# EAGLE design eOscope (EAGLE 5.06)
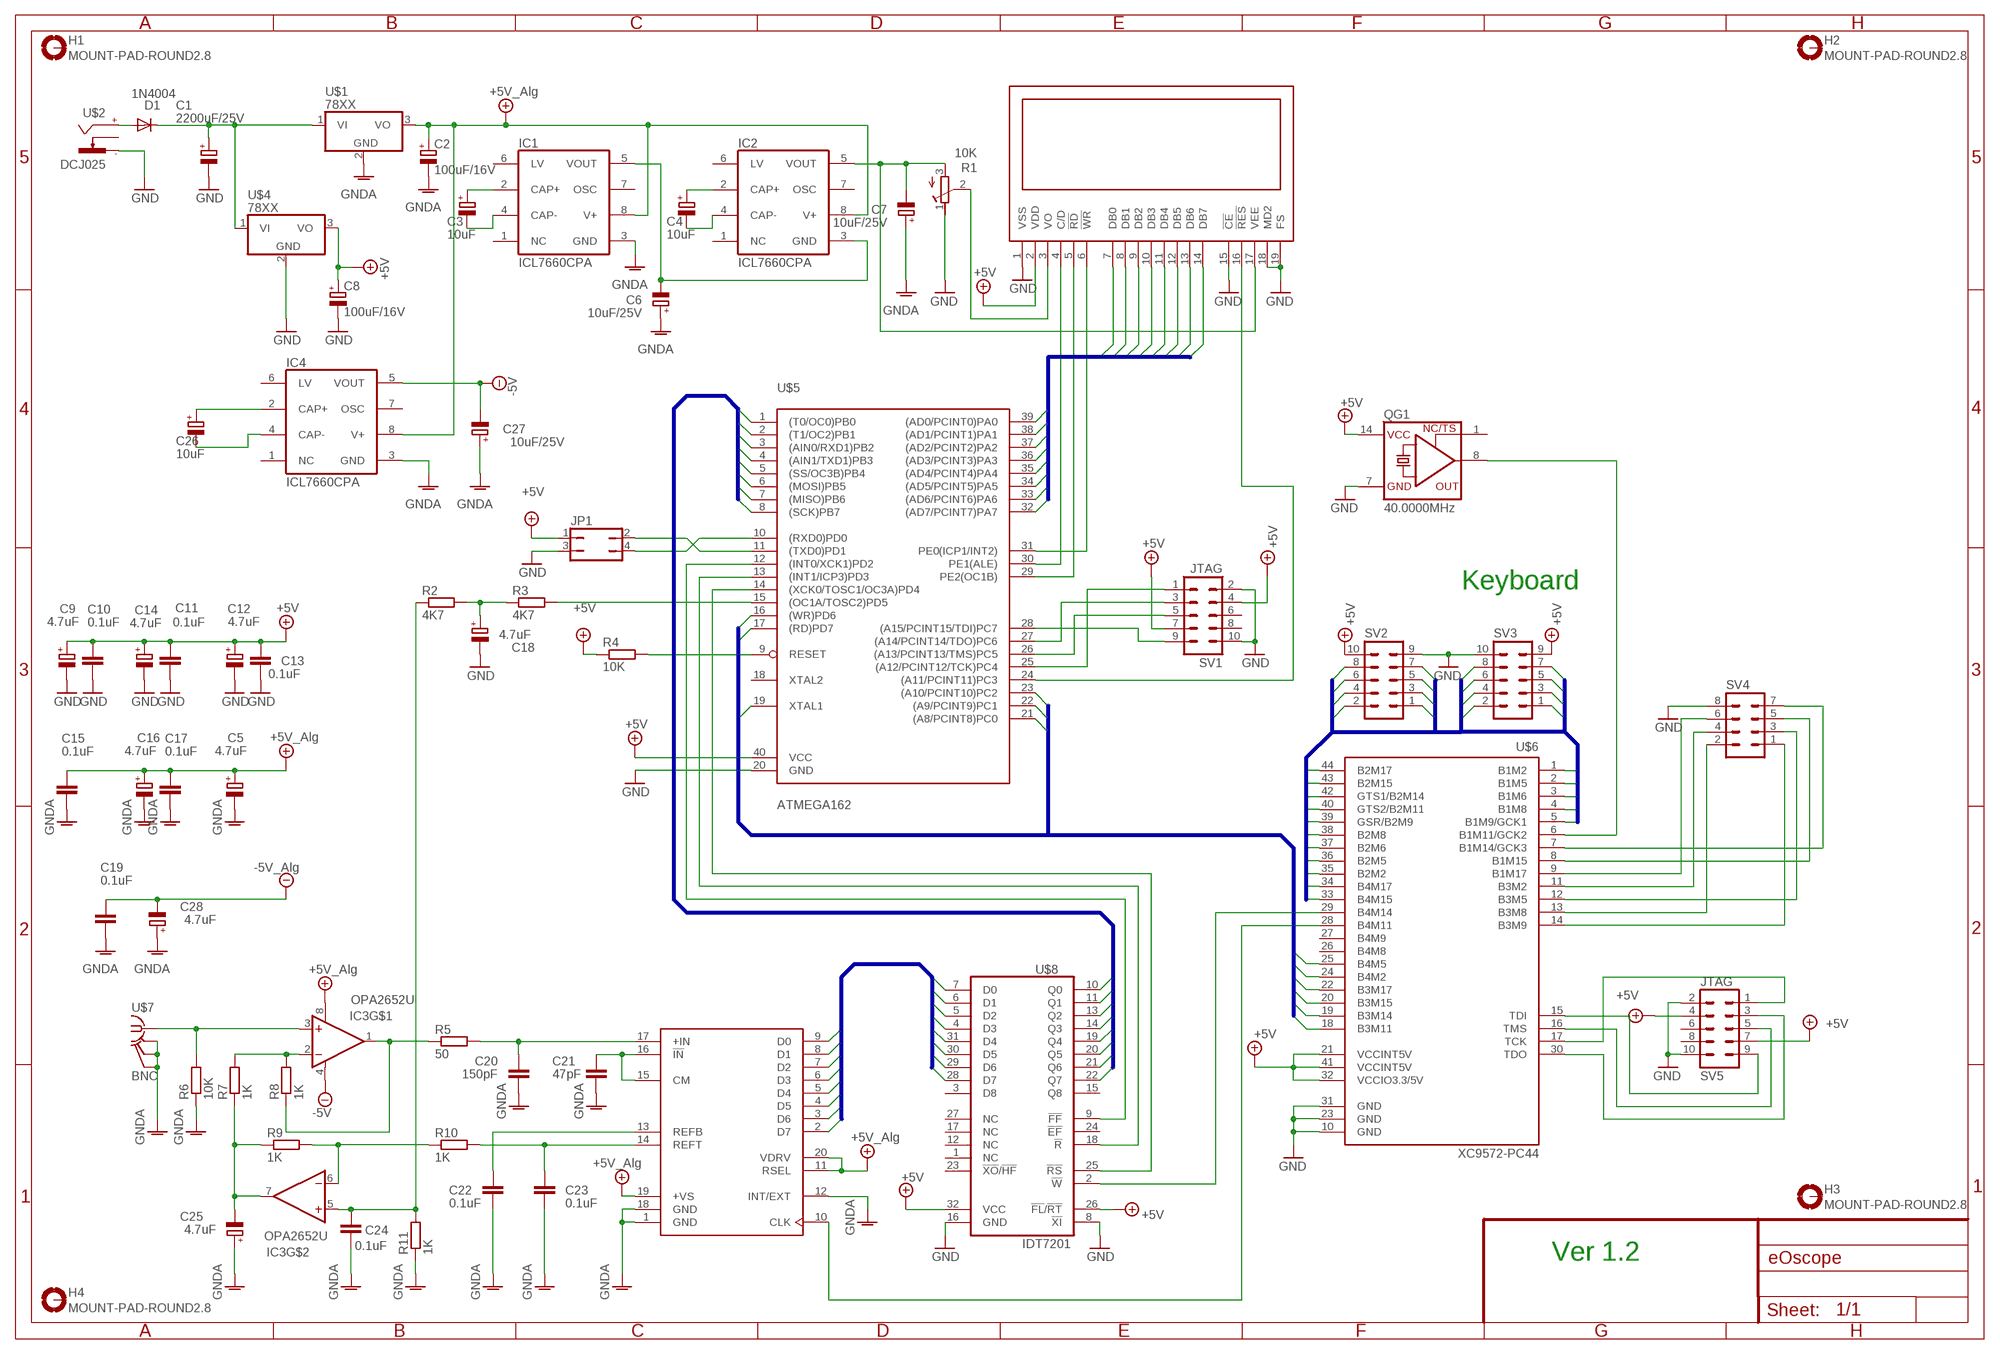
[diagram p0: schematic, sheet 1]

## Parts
C1  2200uF/25V  CPOL-EUE7.5-16  [E7,5-16]
C2  100uF/16V  CPOL-EUE2.5-5  [E2,5-5]
C3  10uF  CPOL-EUE2.5-5  [E2,5-5]
C4  10uF  CPOL-EUE2.5-5  [E2,5-5]
C5  4.7uF  CPOL-EUTT2D4  [TT2D4]
C6  10uF/25V  CPOL-EUE2.5-5  [E2,5-5]
C7  10uF/25V  CPOL-EUE2.5-5  [E2,5-5]
C8  100uF/16V  CPOL-EUE2.5-5  [E2,5-5]
C9  4.7uF  CPOL-EUTT2D4  [TT2D4]
C10  0.1uF  C-EU050-030X075  [C050-030X075]
C11  0.1uF  C-EU050-030X075  [C050-030X075]
C12  4.7uF  CPOL-EUTT2D4  [TT2D4]
C13  0.1uF  C-EU050-030X075  [C050-030X075]
C14  4.7uF  CPOL-EUTT3D5  [TT2D5]
C15  0.1uF  C-EU050-030X075  [C050-030X075]
C16  4.7uF  CPOL-EUTT2D4  [TT2D4]
C17  0.1uF  C-EU050-030X075  [C050-030X075]
C18  4.7uF  CPOL-EUTT2D4  [TT2D4]
C19  0.1uF  C-EU050-030X075  [C050-030X075]
C20  150pF  C-EU050-030X075  [C050-030X075]
C21  47pF  C-EU050-030X075  [C050-030X075]
C22  0.1uF  C-EU050-030X075  [C050-030X075]
C23  0.1uF  C-EU050-030X075  [C050-030X075]
C24  0.1uF  C-EU050-030X075  [C050-030X075]
C25  4.7uF  CPOL-EUTT2D4  [TT2D4]
C26  10uF  CPOL-EUE2.5-5  [E2,5-5]
C27  10uF/25V  CPOL-EUE2.5-5  [E2,5-5]
C28  4.7uF  CPOL-EUTT2D4  [TT2D4]
D1  1N4004  [DO41-10]
H1  MOUNT-PAD-ROUND2.8  [2,8-PAD]
H2  MOUNT-PAD-ROUND2.8  [2,8-PAD]
H3  MOUNT-PAD-ROUND2.8  [2,8-PAD]
H4  MOUNT-PAD-ROUND2.8  [2,8-PAD]
IC1  ICL7660CPA  [DIL08]
IC2  ICL7660CPA  [DIL08]
IC3  OPA2652U  OPA2650U  [SO-08]
IC4  ICL7660CPA  [DIL08]
JP1  JP2Q  [JP2Q]
QG1  40.0000MHz  XO-14  [DIL14S]
R1  10K  R-TRIMMT18  [RTRIMT18]
R2  4K7  R-EU_0207/7  [0207/7]
R3  4K7  R-EU_0207/10  [0207/10]
R4  10K  R-EU_0207/7  [0207/7]
R5  50  R-EU_0207/7  [0207/7]
R6  10K  R-EU_0207/7  [0207/7]
R7  1K  R-EU_0207/7  [0207/7]
R8  1K  R-EU_0207/7  [0207/7]
R9  1K  R-EU_0207/7  [0207/7]
R10  1K  R-EU_0207/7  [0207/7]
R11  1K  R-EU_0207/7  [0207/7]
SV1  JTAG  MA05-2  [MA05-2]
SV2  MA05-2  [MA05-2]
SV3  MA05-2  [MA05-2]
SV4  MA04-2  [MA04-2]
SV5  JTAG  MA05-2  [MA05-2]
U$1  78XX  [TO220V]
U$2  DCJ025  [DCJ025]
U$3  T6963  [MA10-2]
U$4  78XX  [TO220V]
U$5  ATMEGA162  [DIL40]
U$6  XC9572-PC44  [PLCC-S44]
U$7  BNC  [BNC]
U$8  IDT7201  [S32]
U$9  ADS830  [SSOP20]

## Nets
+5V: C8.+ C9.+ C10.1 C11.1 C12.+ C13.1 C14.+ JP1.1 QG1.14(VCC) R4.1 SV1.4 SV1.7 SV2.10 SV3.9 SV5.4 SV5.7 U$3.2(VDD) U$4.3(VO) U$5.40(VCC) U$6.21(VCCINT5V) U$6.32(VCCIO3.3/5V) U$6.41(VCCINT5V) U$8.26(!FL!/!RT) U$8.32(VCC)
+5V/1: C2.+ C5.+ C15.1 C16.+ C17.1 IC1.8(V+) IC2.8(V+) IC3.8(V+) IC4.8(V+) U$1.3(VO) U$9.11(RSEL) U$9.19(+VS) U$9.20(VDRV) ; supply symbol labelled +5V_Alg
-5V: C19.1 C27.- C28.- IC3.4(V-) IC4.5(VOUT) ; supply symbol labelled -5V_Alg
B0: U$5.1((T0/OC0)PB0) U$8.22(Q7)
B1: U$5.2((T1/OC2)PB1) U$8.21(Q6)
B2: U$5.3((AIN0/RXD1)PB2) U$8.20(Q5)
B3: U$5.4((AIN1/TXD1)PB3) U$8.19(Q4)
B4: U$5.5((SS/OC3B)PB4) U$8.14(Q3)
B5: U$5.6((MOSI)PB5) U$8.13(Q2)
B6: U$5.7((MISO)PB6) U$8.11(Q1)
B7: U$5.8((SCK)PB7) U$8.10(Q0)
D0: U$8.28(D7) U$9.9(D0)
D1: U$8.29(D6) U$9.8(D1)
D2: U$8.30(D5) U$9.7(D2)
D3: U$8.31(D4) U$9.6(D3)
D4: U$8.4(D3) U$9.5(D4)
D5: U$8.5(D2) U$9.4(D5)
D6: U$8.6(D1) U$9.3(D6)
D7: U$8.7(D0) U$9.2(D7)
DB0: U$3.7(DB0) U$5.39((AD0/PCINT0)PA0)
DB1: U$3.8(DB1) U$5.38((AD1/PCINT1)PA1)
DB2: U$3.9(DB2) U$5.37((AD2/PCINT2)PA2)
DB3: U$3.10(DB3) U$5.36((AD3/PCINT3)PA3)
DB4: U$3.11(DB4) U$5.35((AD4/PCINT4)PA4)
DB5: U$3.12(DB5) U$5.34((AD5/PCINT5)PA5)
DB6: U$3.13(DB6) U$5.33((AD6/PCINT6)PA6)
DB7: U$3.14(DB7) U$5.32((AD7/PCINT7)PA7)
E0: SV2.1 U$6.4(B1M8)
E1: SV2.2 U$6.5(B1M9/GCK1)
E2: SV2.3 U$6.2(B1M5)
E3: SV2.4 U$6.3(B1M6)
E4: SV2.5 U$6.44(B2M17)
E5: SV2.6 U$6.1(B1M2)
E6: SV2.7 U$6.42(GTS1/B2M14)
E7: SV2.8 U$6.43(B2M15)
E8: SV3.1 U$6.33(B4M15)
E9: SV3.2 U$6.34(B4M17)
E10: SV3.3 U$6.35(B2M2)
E11: SV3.4 U$6.36(B2M5)
E12: SV3.5 U$6.37(B2M6)
E13: SV3.6 U$6.38(B2M8)
E14: SV3.7 U$6.39(GSR/B2M9)
E15: SV3.8 U$6.40(GTS2/B2M11)
F1: U$5.16((WR)PD6) U$6.24(B4M2)
F2: U$5.17((RD)PD7) U$6.22(B3M17)
F3: U$5.23((A10/PCINT10)PC2) U$6.25(B4M5)
F4: U$5.22((A9/PCINT9)PC1) U$6.20(B3M15)
F5: U$5.21((A8/PCINT8)PC0) U$6.18(B3M11)
F6: U$5.19(XTAL1) U$6.19(B3M14)
GND: C1.- C8.- C9.- C10.2 C11.2 C12.- C13.2 C14.- C18.- JP1.3 QG1.7(GND) R1.1(A) SV1.2 SV1.10 SV2.9 SV3.10 SV4.8 SV5.2 SV5.10 U$2.P$3(-) U$3.1(VSS) U$3.15(!CE) U$3.18(MD2) U$3.19(FS) U$4.2(GND) U$5.20(GND) U$6.10(GND) U$6.23(GND) U$6.31(GND) U$8.8(!XI) U$8.16(GND)
GNDA: C2.- C5.- C6.+ C7.+ C15.2 C16.- C17.2 C19.2 C20.2 C21.2 C22.2 C23.2 C24.2 C25.+ C27.+ C28.+ IC1.3(GND) IC4.3(GND) R6.1 R11.1 U$1.2(GND) U$7.GND U$7.P$3 U$7.P$4 U$9.1(GND) U$9.12(INT/EXT) U$9.18(GND)
N$1: C1.+ D1.C U$1.1(VI) U$4.1(VI)
N$2: R1.2(S) U$3.3(VO)
N$3: U$3.4(C/D) U$5.30(PE1(ALE))
N$4: C3.+ IC1.2(CAP+)
N$5: C7.- IC2.5(VOUT) R1.3(E) U$3.17(VEE)
N$6: U$3.5(!RD) U$5.29(PE2(OC1B))
N$7: D1.A U$2.P$1(+)
N$8: SV5.9 U$6.15(TDI)
N$9: SV5.3 U$6.30(TDO)
N$10: U$3.6(!WR) U$5.31(PE0(ICP1/INT2))
N$11: SV4.1 U$6.14(B3M9)
N$12: U$5.12((INT0/XCK1)PD2) U$8.9(!FF)
N$13: QG1.8(OUT) U$6.6(B1M11/GCK2)
N$14: U$6.29(B4M14) U$8.2(!W)
N$15: U$5.13((INT1/ICP3)PD3) U$8.18(!R)
N$16: SV4.3 U$6.12(B3M5)
N$17: SV4.2 U$6.13(B3M8)
N$18: U$5.14((XCK0/TOSC1/OC3A)PD4) U$8.25(!RS)
N$19: C3.- IC1.4(CAP-)
N$20: R4.2 U$5.9(RESET)
N$21: SV4.4 U$6.11(B3M2)
N$22: U$3.16(!RES) U$5.24((A11/PCINT11)PC3)
N$23: IC3.1(OUT) R5.1 R8.1
N$24: C22.1 U$9.13(REFB)
N$25: IC3.6(-IN) R9.2 R10.1
N$26: C20.1 R5.2 U$9.17(+IN)
N$27: C25.- IC3.7(OUT) R7.1 R9.1
N$28: IC3.3(+IN) R6.2 U$7.1
N$29: IC3.2(-IN) R7.2 R8.2
N$30: R3.2 U$5.15((OC1A/TOSC2)PD5)
N$31: C23.1 R10.2 U$9.14(REFT)
N$32: C21.1 U$9.15(CM) U$9.16(!IN)
N$33: C18.+ R2.2 R3.1
N$34: SV5.5 U$6.16(TMS)
N$35: SV1.1 U$5.25((A12/PCINT12/TCK)PC4)
N$36: SV1.3 U$5.27((A14/PCINT14/TDO)PC6)
N$37: SV1.5 U$5.26((A13/PCINT13/TMS)PC5)
N$38: SV1.9 U$5.28((A15/PCINT15/TDI)PC7)
N$39: SV5.1 U$6.17(TCK)
N$40: SV4.6 U$6.9(B1M17)
N$41: U$6.28(B4M11) U$9.10(CLK)
N$42: C26.+ IC4.2(CAP+)
N$43: SV4.7 U$6.7(B1M14/GCK3)
N$44: SV4.5 U$6.8(B1M15)
N$45: C4.+ IC2.2(CAP+)
N$47: C4.- IC2.4(CAP-)
N$52: C26.- IC4.4(CAP-)
N$53: JP1.4 U$5.10((RXD0)PD0)
N$54: JP1.2 U$5.11((TXD0)PD1)
N$60: C6.- IC1.5(VOUT) IC2.3(GND)
N$64: C24.1 IC3.5(+IN) R2.1 R11.2
Unconnected: H1.B2,8(MOUNT) H2.B2,8(MOUNT) H3.B2,8(MOUNT) H4.B2,8(MOUNT) IC1.1(NC) IC1.6(LV) IC1.7(OSC) IC2.1(NC) IC2.6(LV) IC2.7(OSC) IC4.1(NC) IC4.6(LV) IC4.7(OSC) QG1.1(TS) SV1.6 SV1.8 SV5.6 SV5.8 U$2.P$2(K1) U$2.P$4(K2) U$5.18(XTAL2) U$6.26(B4M8) U$6.27(B4M9) U$8.1(NC) U$8.3(D8) U$8.12(NC) U$8.15(Q8) U$8.17(NC) U$8.23(!XO!/!HF) U$8.24(!EF) U$8.27(NC)

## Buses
DB[0..7]
D[0..7]
B[0..7]
F[0..6]
E[0..15]

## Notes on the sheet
- Keyboard
- Ver 1.2

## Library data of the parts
C1-C9 C12 C16 C18 C25-C28 = rcl:CPOL-EU: POLARIZED CAPACITOR, European symbol
C10 C11 C13 C15 C17 C19-C24 = rcl:C-EU: CAPACITOR, European symbol
C14 = eOscope:CPOL-EUTT3D5
D1 = diode:1N4004: DIODE
H1-H4 = holes:MOUNT-PAD-ROUND: MOUNTING PAD, round
IC1 IC2 IC4 = maxim:ICL7660CPA: VOLTAGE CONVERTER
IC3 = burr-brown:OPA2650U: Dual Wideband, Low Power Voltage Feedback Operational Amplifier
JP1 = jumper:JP2Q: JUMPER
QG1 = crystal:XO-: CRYSTAL
R1 = rcl:R-TRIMM: Trimm resistor
R2-R11 = rcl:R-EU_: RESISTOR, European symbol
SV1-SV3 SV5 = con-lstb:MA05-2: PIN HEADER
SV4 = con-lstb:MA04-2: PIN HEADER
U$1 U$4 = eOscope:78XX
U$2 = con-jack:DCJ025: DC power connector: +V at inner plug GND at outer plug Designed by: daci@eoscope.ro Copyright daci@eoscope.ro 2006
U$3 = eOscope:T6963
U$5 = eOscope:ATMEGA162: 35 GPIO, JTAG, 2 UART, 16 pin change interrupt
U$6 = eOscope:XC9572-PC44
U$7 = eOscope:BNC
U$8 = eOscope:IDT7201
U$9 = eOscope:ADS830

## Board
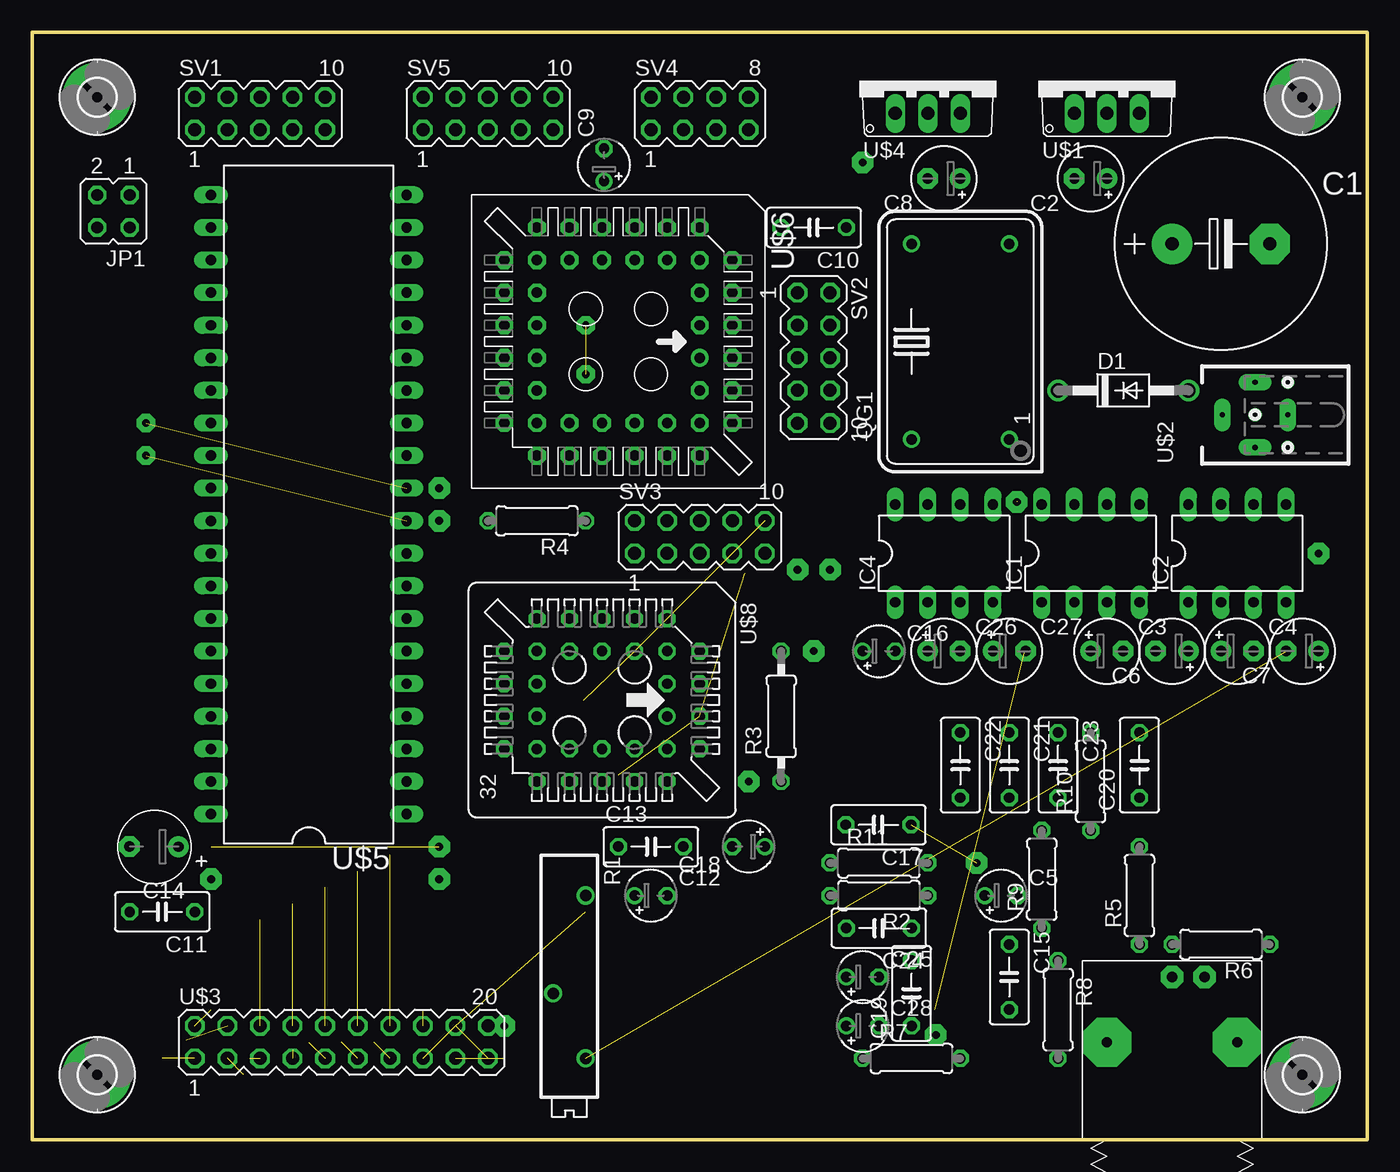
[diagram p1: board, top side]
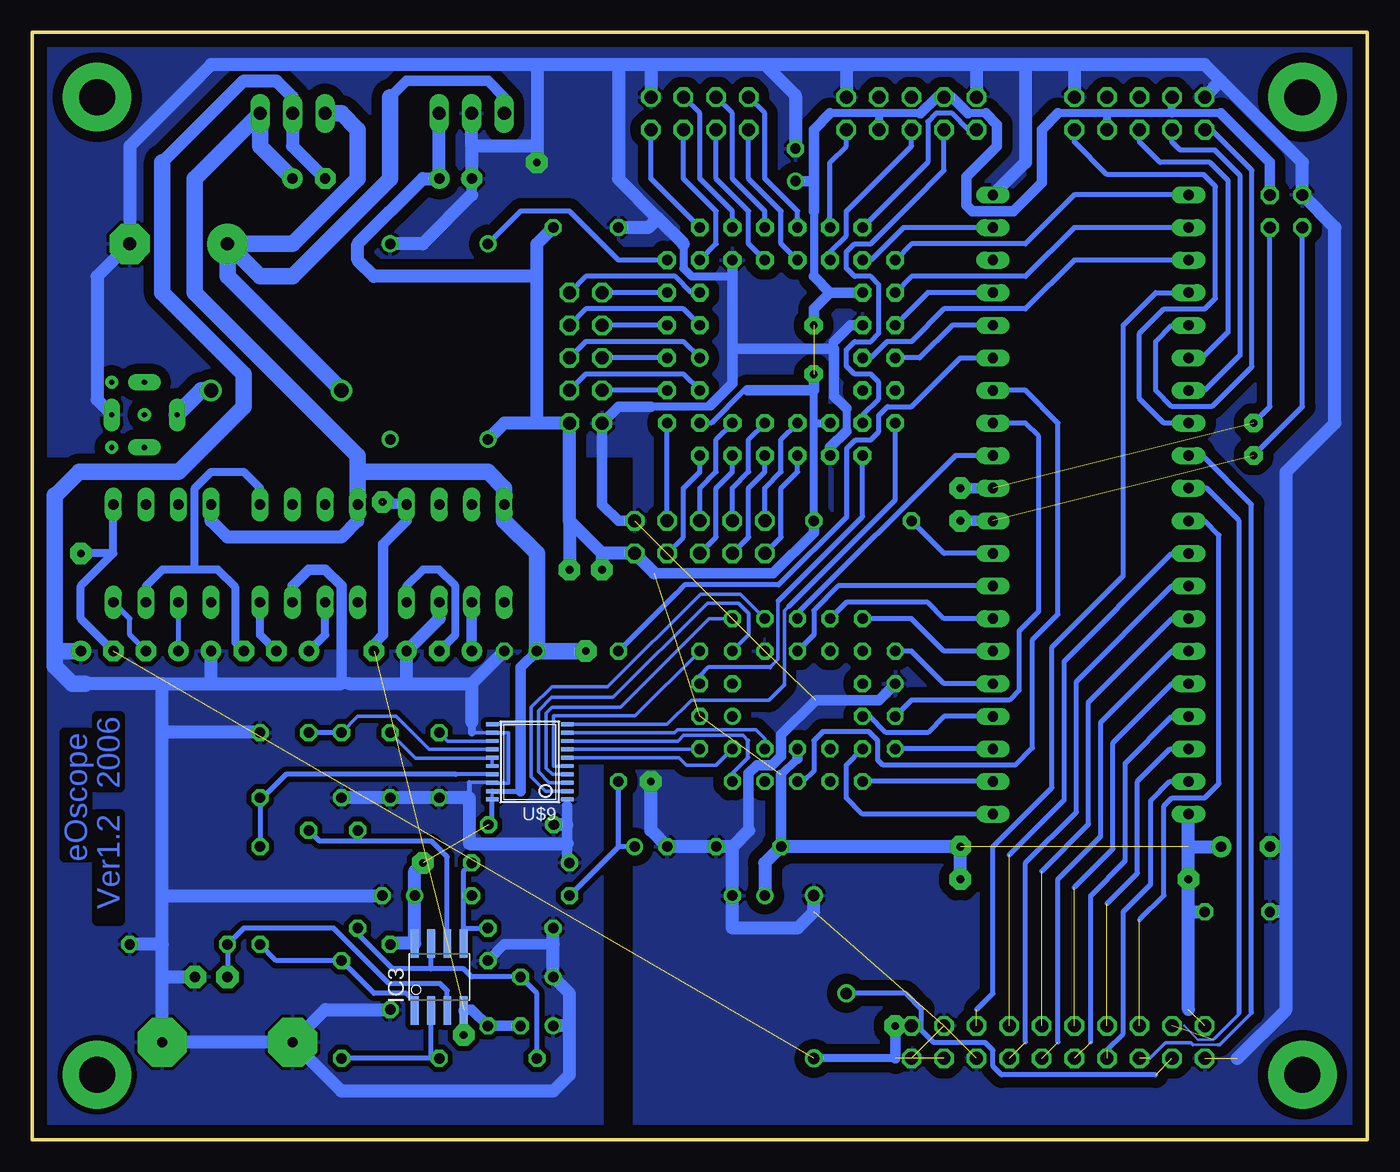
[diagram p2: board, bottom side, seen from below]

Size 104.13 x 86.35 mm. Coordinates in mm from the lower left corner, seen from the top.
Outline: 0,0 104.13,0 104.13,86.35 0,86.35 0,0
Copper layers (1*16): Top 0.035mm / dielectric 1.5mm / Bottom 0.035mm
Design rules "default": minimum track width 0.2mm, minimum drill 0.3mm, track to track 8mil, track to pad 8mil, pad to pad 8mil, via to via 8mil, smd to smd 8mil, copper to edge 40mil, drill to drill 8mil, minimum pad ring 10mil, minimum via ring 8mil, stop-mask expansion 4mil, vias tented up to drill 0mil, thermal gap 10mil

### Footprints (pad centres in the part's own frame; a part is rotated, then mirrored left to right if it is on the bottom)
E7,5-16 = drill 1.016 pad 3.15 round: + -3.81,0 | drill 1.016 pad 3.15 octagon: - 3.81,0
E2,5-5 = drill 0.813 pad 1.6 round: + -1.27,0 | drill 0.813 pad 1.6 octagon: - 1.27,0
TT2D4 = drill 0.813 round: + -1.27,0 | drill 0.813 octagon: - 1.27,0
C050-030X075 = drill 0.813 octagon: 1 -2.54,0; 2 2.54,0
TT2D5 = drill 0.813 pad 1.6 round: + -1.909,0.046 | drill 0.813 pad 1.6 octagon: - 1.915,0.037
DO41-10 = drill 1.118 round: A 5.08,0; C -5.08,0
2,8-PAD = drill 2.8 pad 5.334 round: B2,8 0,0
DIL08 = drill 0.813 long: 1 -3.81,-3.81; 2 -1.27,-3.81; 3 1.27,-3.81; 4 3.81,-3.81; 5 3.81,3.81; 6 1.27,3.81; 7 -1.27,3.81; 8 -3.81,3.81
SO-08 = smd 0.61 x 2.21: 1 -1.905,-2.616; 2 -0.635,-2.616; 3 0.635,-2.616; 4 1.905,-2.616; 5 1.905,2.616; 6 0.635,2.616; 7 -0.635,2.616; 8 -1.905,2.616
JP2Q = drill 0.914 octagon: 1 -1.27,-1.27; 2 -1.27,1.27; 3 1.27,-1.27; 4 1.27,1.27
DIL14S = drill 0.813 round: 1 -7.62,-3.81; 7 7.62,-3.81; 8 7.62,3.81; 14 -7.62,3.81
RTRIMT18 = drill 0.9 round: 1 -7.62,1.27; 2 0,-1.27; 3 5.08,1.27
0207/7 = drill 0.813 octagon: 1 -3.81,0; 2 3.81,0
0207/10 = drill 0.813 octagon: 1 -5.08,0; 2 5.08,0
MA05-2 = drill 1.016 octagon: 1 -5.08,-1.27; 2 -5.08,1.27; 3 -2.54,-1.27; 4 -2.54,1.27; 5 0,-1.27; 6 0,1.27; 7 2.54,-1.27; 8 2.54,1.27; 9 5.08,-1.27; 10 5.08,1.27
MA04-2 = drill 1.016 octagon: 1 -3.81,-1.27; 2 -3.81,1.27; 3 -1.27,-1.27; 4 -1.27,1.27; 5 1.27,-1.27; 6 1.27,1.27; 7 3.81,-1.27; 8 3.81,1.27
TO220V = drill 1.016 long: 1 -2.54,-2.54; 2 0,-2.54; 3 2.54,-2.54
DCJ025 = drill 0.4 pad 1.27 long: P$1 0,0; P$2 2.54,-2.54; P$3 0,-5.08; P$4 -2.54,-2.54 | drill 0.4 pad 1.016 round: P$5 -2.54,-5.08; P$6 2.54,-5.08; P$7 0,-2.54
MA10-2 = drill 1.016 octagon: 1 -11.43,-1.27; 2 -11.43,1.27; 3 -8.89,-1.27; 4 -8.89,1.27; 5 -6.35,-1.27; 6 -6.35,1.27; 7 -3.81,-1.27; 8 -3.81,1.27; 9 -1.27,-1.27; 10 -1.27,1.27; 11 1.27,-1.27; 12 1.27,1.27; 13 3.81,-1.27; 14 3.81,1.27; 15 6.35,-1.27; 16 6.35,1.27; 17 8.89,-1.27; 18 8.89,1.27; 19 11.43,-1.27; 20 11.43,1.27
DIL40 = drill 0.813 long: 1 -22.86,-7.62; 2 -20.32,-7.62; 3 -17.78,-7.62; 4 -15.24,-7.62; 5 -12.7,-7.62; 6 -10.16,-7.62; 7 -7.62,-7.62; 8 -5.08,-7.62; 9 -2.54,-7.62; 10 0,-7.62; 11 2.54,-7.62; 12 5.08,-7.62; 13 7.62,-7.62; 14 10.16,-7.62; 15 12.7,-7.62; 16 15.24,-7.62; 17 17.78,-7.62; 18 20.32,-7.62; 19 22.86,-7.62; 20 25.4,-7.62; 21 25.4,7.62; 22 22.86,7.62; 23 20.32,7.62; 24 17.78,7.62; 25 15.24,7.62; 26 12.7,7.62; 27 10.16,7.62; 28 7.62,7.62; 29 5.08,7.62; 30 2.54,7.62; 31 0,7.62; 32 -2.54,7.62; 33 -5.08,7.62; 34 -7.62,7.62; 35 -10.16,7.62; 36 -12.7,7.62; 37 -15.24,7.62; 38 -17.78,7.62; 39 -20.32,7.62; 40 -22.86,7.62
PLCC-S44 = drill 0.813 pad 1.397 round: 1 1.27,6.35 | drill 0.813 pad 1.397 octagon: 2 -1.27,8.89; 3 -1.27,6.35; 4 -3.81,8.89; 5 -3.81,6.35; 6 -6.35,8.89; 7 -8.89,6.35; 8 -6.35,6.35; 9 -8.89,3.81; 10 -6.35,3.81; 11 -8.89,1.27; 12 -6.35,1.27; 13 -8.89,-1.27; 14 -6.35,-1.27; 15 -8.89,-3.81; 16 -6.35,-3.81; 17 -8.89,-6.35; 18 -6.35,-8.89; 19 -6.35,-6.35; 20 -3.81,-8.89; 21 -3.81,-6.35; 22 -1.27,-8.89; 23 -1.27,-6.35; 24 1.27,-8.89; 25 1.27,-6.35; 26 3.81,-8.89; 27 3.81,-6.35; 28 6.35,-8.89; 29 8.89,-6.35; 30 6.35,-6.35; 31 8.89,-3.81; 32 6.35,-3.81; 33 8.89,-1.27; 34 6.35,-1.27; 35 8.89,1.27; 36 6.35,1.27; 37 8.89,3.81; 38 6.35,3.81; 39 8.89,6.35; 40 6.35,8.89; 41 6.35,6.35; 42 3.81,8.89; 43 3.81,6.35; 44 1.27,8.89
BNC = drill 0.8 pad 1.778 octagon: 1 -5.08,0; GND -5.08,2.54 | drill 0.8 pad 3.81 octagon: P$3 0,-5.08; P$4 0,5.08
S32 = drill 0.813 round: 1 1.27,5.08 | drill 0.813 octagon: 2 -1.27,7.62; 3 -1.27,5.08; 4 -3.81,7.62; 5 -6.35,5.08; 6 -3.81,5.08; 7 -6.35,2.54; 8 -3.81,2.54; 9 -6.35,0; 10 -3.81,0; 11 -6.35,-2.54; 12 -3.81,-2.54; 13 -6.35,-5.08; 14 -3.81,-7.62; 15 -3.81,-5.08; 16 -1.27,-7.62; 17 -1.27,-5.08; 18 1.27,-7.62; 19 1.27,-5.08; 20 3.81,-7.62; 21 6.35,-5.08; 22 3.81,-5.08; 23 6.35,-2.54; 24 3.81,-2.54; 25 6.35,0; 26 3.81,0; 27 6.35,2.54; 28 3.81,2.54; 29 6.35,5.08; 30 3.81,7.62; 31 3.81,5.08; 32 1.27,7.62
SSOP20 = smd 0.305 x 0.991: 1 -2.925,-2.918; 2 -2.275,-2.918; 3 -1.625,-2.918; 4 -0.975,-2.918; 5 -0.325,-2.918; 6 0.325,-2.918; 7 0.975,-2.918; 8 1.625,-2.918; 9 2.275,-2.918; 10 2.925,-2.918; 11 2.925,2.918; 12 2.275,2.918; 13 1.625,2.918; 14 0.975,2.918; 15 0.325,2.918; 16 -0.325,2.918; 17 -0.975,2.918; 18 -1.625,2.918; 19 -2.275,2.918; 20 -2.925,2.918

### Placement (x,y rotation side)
C1  92.7,69.84 0 top
C2  82.54,74.92 180 top
C3  83.81,38.1 0 top
C4  93.97,38.1 0 top
C5  75.56,19.05 0 top
C6  88.89,38.1 180 top
C7  99.05,38.1 180 top
C8  71.11,74.92 180 top
C9  44.6,76 90 top
C10  60.95,71.12 180 top
C11  10.15,17.77 180 top
C12  48.25,19.05 0 top
C13  48.25,22.86 0 top
C14  9.52,22.89 180 top
C15  76.19,12.7 270 top
C16  66.03,38.1 0 top
C17  65.99,24.56 180 top
C18  55.87,22.86 180 top
C19  68.57,11.43 90 top
C20  86.35,29.2 90 top
C21  76.19,29.2 270 top
C22  72.38,29.2 270 top
C23  80,29.2 270 top
C24  66.03,16.5 180 top
C25  64.76,12.7 0 top
C26  71.11,38.1 0 top
C27  76.19,38.1 0 top
C28  64.76,8.88 0 top
D1  85.08,58.42 0 top
H1  5.07,5.08 0 top
H2  5.07,81.28 0 top
H3  99.05,81.28 0 top
H4  99.05,5.08 0 top
IC1  82.54,45.72 0 top
IC2  93.97,45.72 0 top
IC3  72.38,12.7 0 bottom
IC4  71.11,45.72 0 top
JP1  6.34,72.39 180 top
QG1  72.38,62.23 90 top
R1  41.9,11.43 270 top
R2  66.03,19.05 180 top
R3  58.41,33.02 90 top
R4  39.36,48.26 180 top
R5  86.35,19.05 90 top
R6  92.7,15.23 180 top
R7  68.57,6.35 0 top
R8  80,10.16 270 top
R9  78.73,20.32 90 top
R10  82.54,27.93 90 top
R11  66.03,21.59 0 top
SV1  17.77,80.01 0 top
SV2  60.95,60.96 270 top
SV3  52.06,46.98 0 top
SV4  52.06,80.01 0 top
SV5  35.55,80.01 0 top
U$1  83.81,82.55 0 top
U$2  92.82,56.51 90 top
U$3  24.12,7.62 0 top
U$4  69.84,82.55 0 top
U$5  21.58,48.26 90 top
U$6  45.71,62.23 270 top
U$7  88.89,7.62 270 top
U$8  44.44,34.29 270 top
U$9  65.31,29.46 90 bottom

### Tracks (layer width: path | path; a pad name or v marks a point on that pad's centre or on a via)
+5V  (via drill 0.6 pad 1.68)  (5 unrouted)
  Bottom 0.305: 46.35,44.17
  Bottom 0.406: U$6.41 51.15,55.88 48.61,58.42 48.33,58.42
  Bottom 0.61: 45.71,28.45 44.44,29.72 | 20.31,80.01 SV1.7 | 43.17,55.88 43.17,58.42 | 43.17,55.88 U$6.32 | 15.23,80.01 SV1.4 | 15.23,80.01 20.31,80.01 | R4.1 43.17,55.88 | 11.42,80.01 15.23,80.01 | 20.31,80.01 24.12,80.01 | 38.09,80.01 41.9,80.01 | 34.84,80.01 38.09,80.01 | 38.09,80.01 SV5.7 | 29.76,80.01 31.15,80.01 | 43.17,72.39 43.17,67.3
  Bottom 0.813: 41.9,66.03 U$6.21 | 43.17,67.3 41.9,66.03 | 44.44,29.72 U$8.26 | 41.9,66.03 43.17,64.77 43.17,63.5 | 43.17,74.73 43.17,78.73 41.9,80.01 | 43.17,59.69 43.17,58.42 48.33,58.42 | 24.12,80.01 25.39,78.73 25.39,74.61 27.62,72.39 30.79,72.39 31.27,72.86 31.27,75.08 28.89,77.47 28.89,79.13 29.76,80.01 | 34.84,80.01 33.57,81.28 SV5.4 32.42,81.28 31.15,80.01 | 43.17,74.73 C9.+ | C13.1 45.71,28.45 | R4.1 43.13,48.22 43.17,48.18 43.17,47.34 46.35,44.17 55.6,44.17 | 43.17,74.73 43.17,72.39 | 11.42,80.01 7.61,76.2 JP1.1
  Bottom 1.016: 62.22,48.26 SV2.10 64.76,55.88 | 59.68,45.72 62.22,48.26 | 59.68,45.72 SV3.9 55.6,44.17 | 64.76,55.88 67.3,55.88 QG1.14 | C10.1 64.76,69.84 64.76,67.3 | 64.76,55.88 64.76,67.3 | U$4.3 C8.+ 73.65,74.92 78.73,69.84 78.73,68.58 77.46,67.3 64.76,67.3 | 62.22,48.26 v62.22,44.45 | 59.68,45.72 v59.68,44.45 | C12.+ 46.98,21.59 C13.1 v31.74,22.86 v31.74,20.32 | 13.96,17.77 v13.96,20.32 13.96,22.86 | 13.96,17.77 C11.1 | 13.96,10.16 13.96,17.77 | 13.96,22.86 U$5.40 | C14.+ 13.96,22.86
+5V/1  (via drill 0.6 pad 1.68)  (1 unrouted)
  Bottom 0.254: U$9.11 arc-90 U$9.11 66.04,32.39 66.03,32.38 | U$9.19 68.26,27.16 68.26,26.55 U$9.20
  Bottom 0.406: IC3.8 74.29,15.23 | U$9.19 66.03,27.18 | C17.1 68.26,24.84 68.26,26.55
  Bottom 0.813: 66.03,27.18 66.03,32.38 66.03,36.83 C16.+ | 76.12,15.31 C15.1
  Bottom 1.016: IC1.8 78.73,48.26 80,46.98 88.89,46.98 90.16,48.26 IC2.8 | 76.12,15.31 IC3.8 C5.+ 74.29,20.95 v73.65,21.59
  Bottom 1.27: 78.73,52.07 IC1.8 | 78.73,52.07 78.73,53.34 91.43,66.03 91.43,74.92 U$1.3 86.35,77.47 C2.+ | 78.73,52.07 68.57,52.07 67.3,50.8 IC4.8 67.3,48.26 64.76,45.72 C16.+ v60.95,38.1
-5V  (1 unrouted)
  Bottom 0.813: IC4.5 74.92,48.26 76.75,46.43 76.75,39.37 77.42,38.69 77.42,38.1 C27.- | IC3.4 70.4,10.16 69.84,10.16 C19.1 C28.-
B0
  Bottom 0.406: U$8.22 40.63,29.2 40.63,26.66 39.36,25.39 U$5.1
B1
  Bottom 0.406: U$5.2 U$8.21
B2
  Bottom 0.406: U$5.3 U$8.20
B3
  Bottom 0.406: U$5.4 33.01,33.02 34.28,31.75 37.54,31.75 38.81,33.02 U$8.19
B4
  Bottom 0.406: U$5.5 33.01,35.55 35.55,38.1 U$8.14
B5
  Bottom 0.406: U$8.13 35.55,40.64 33.01,38.1 U$5.6
B6
  Bottom 0.406: U$5.7 33.01,40.64 34.28,41.91 40.63,41.91 U$8.11
B7
  Bottom 0.406: U$8.10 43.17,39.37 43.17,41.27 41.27,43.18 U$5.8
D0
  Bottom 0.254: U$9.9 54.05,31.75 53.81,31.98 47.7,31.98 46.98,31.27 U$8.28
D1
  Bottom 0.254: 48.29,31.12 48.69,31.52 53.33,31.52 53.76,31.09 62.42,31.09 | 62.42,31.09 62.42,31.07 | 62.42,31.09 U$9.8
  Bottom 0.305: U$8.29 49.52,28.57 48.29,29.8 48.29,31.12
D2
  Bottom 0.254: 52.1,30.44 U$9.7
  Bottom 0.406: 52.1,30.44 U$8.30
D3
  Bottom 0.254: 50.79,29.2 53.1,29.2 53.68,29.79 62.41,29.79 | 62.41,29.79 62.42,29.8 | 62.41,29.79 U$9.6
  Bottom 0.305: U$8.31 50.79,29.2
D4
  Bottom 0.254: U$8.4 57.1,33.05 | U$9.5 62.38,29.13 63.45,29.13 63.45,33.05 57.1,33.05 | U$9.5 | 57.1,33.05
D5
  Bottom 0.254: U$8.5 51.35,40.64 58.25,33.73 63.58,33.73 63.58,33.72 64.05,33.25 64.05,33.26 64.06,33.26 64.06,28.98 | 64.06,28.98 | 64.06,28.98 63.56,28.48 63.54,28.48 63.53,28.49 U$9.4 | 64.06,28.98 64.05,28.97
D6
  Bottom 0.254: 51.47,41.83 58.81,34.48 63.61,34.48 64.64,33.45 64.64,33.43 | 51.47,41.83 | 49.05,41.83 51.47,41.83 | 63.8,27.84 63.81,27.86 | 63.8,27.84 64.65,28.69 64.65,33.43 64.64,33.43 | U$9.3 63.79,27.84 63.8,27.84 | 64.64,33.43 64.64,33.41
  Bottom 0.305: 49.05,41.83 48.23,41 48.23,39.41 U$8.6 | U$8.6 | U$8.6
D7
  Bottom 0.254: U$8.7 48.89,42.54 52.02,42.54 59.25,35.32 63.6,35.32 65.2,33.72 65.2,28.3 64.09,27.19 U$9.2 | U$9.2 62.38,27.18 | U$9.2
  Bottom 0.305: U$8.7
DB0  (1 unrouted)
  Bottom 0.406: U$5.39 15.39,27.93 16.9,26.43 16.9,19.92 19.04,17.77 19.04,8.29 20.31,7.02
DB1  (1 unrouted)
  Bottom 0.406: U$5.38 15.39,30.47 17.93,27.93 17.93,20.79 | 17.93,20.79 | 17.93,20.79 | 17.93,20.79 | 20.31,18.41 17.93,20.79
DB2  (1 unrouted)
  Bottom 0.406: U$5.37 15.23,33.02 18.88,29.36 18.88,21.74 21.58,19.05 21.58,7.62
DB3  (1 unrouted)
  Bottom 0.406: U$5.36 15.23,35.55 19.84,30.95 19.84,22.7 22.85,19.68
DB4  (1 unrouted)
  Bottom 0.406: U$5.35 15.23,38.1 20.79,32.54 20.79,23.65 24.12,20.32 24.12,7.62
DB5  (1 unrouted)
  Bottom 0.406: U$5.34 15.23,40.64 21.74,34.13 21.74,24.6 25.39,20.95
DB6  (1 unrouted)
  Bottom 0.406: U$5.33 15.23,43.18 22.69,35.71 22.69,25.55 26.66,21.59 26.66,7.62
DB7  (1 unrouted)
  Bottom 0.406: U$5.32 15.23,45.72 23.65,37.3 23.65,26.51 27.93,22.22
E0
  Bottom 0.406: U$6.4 SV2.1
E1
  Bottom 0.406: U$6.5 52.7,66.03 53.97,67.3 60.95,67.3 SV2.2
E2
  Bottom 0.406: U$6.2 SV2.3
E3
  Bottom 0.406: U$6.3 53.33,64.77 60.95,64.77 SV2.4
E4
  Bottom 0.406: U$6.44 SV2.5
E5
  Bottom 0.406: U$6.1 53.33,62.23 60.95,62.23 SV2.6
E6
  Bottom 0.406: U$6.42 SV2.7
E7
  Bottom 0.406: U$6.43 53.33,59.69 60.95,59.69 SV2.8
E8
  Bottom 0.406: U$6.33 44.44,52.07 45.71,50.8 45.71,46.98 SV3.1
E9
  Bottom 0.406: U$6.34 45.71,54.61 45.71,52.07 46.98,50.8 SV3.2
E10
  Bottom 0.406: U$6.35 46.98,52.07 48.25,50.8 48.25,46.98 SV3.3
E11
  Bottom 0.406: U$6.36 48.25,54.61 48.25,52.07 49.52,50.8 SV3.4
E12
  Bottom 0.406: U$6.37 49.52,52.07 50.79,50.8 50.79,46.98 SV3.5
E13
  Bottom 0.406: U$6.38 50.79,54.61 50.79,52.07 52.06,50.8 SV3.6
E14
  Bottom 0.406: U$6.39 52.06,52.07 53.33,50.8 53.33,46.98 SV3.7
E15
  Bottom 0.406: SV3.8 U$6.40
F1
  Bottom 0.406: U$5.16 32.38,63.5 34.92,60.96 U$6.24
F2
  Bottom 0.406: U$5.17 34.28,66.03 U$6.22
F3
  Bottom 0.406: U$5.23 22.85,68.58 26.66,64.77 33.01,64.77 35.55,62.23 37.46,62.23 38.73,60.96 U$6.25
F4
  Bottom 0.406: U$5.22 22.85,71.12 26.66,67.3 35.55,67.3 U$6.20
F5
  Bottom 0.406: U$5.21 22.85,73.66 26.66,69.84 35.55,69.84 U$6.18
F6
  Bottom 0.406: U$5.19 36.19,71.12 38.73,68.58 U$6.19
GND  (via drill 0.6 pad 1.68)  (6 unrouted)
  Bottom 0.406: 41.59,61.67 41.59,62.23
  Bottom 0.6: 51.23,57.26 51.35,57.15
  Bottom 0.61: 40.63,57.03 40.63,55.24 | 49.52,67.3 52.7,67.3 53.33,67.94 53.33,69.84 | 51.35,57.15 55.87,57.15
  Bottom 0.813: U$6.23 40.32,63.5 41.59,62.23 | 40.63,57.03 41.59,57.98 41.59,61.67 49.52,61.67 | 40.63,55.24 41.9,53.97 U$6.31 | 49.52,61.67 49.52,67.3 U$6.10 | U$8.16 38.09,34.29 43.01,34.29 45.71,31.59 45.71,29.92 46.43,29.2 47.62,29.2 | 49.52,61.67 49.52,58.97 51.23,57.26 | SV3.10 58.41,48.26 59.68,49.53 SV2.9 58.41,57.15 55.87,57.15 | 46.94,83.81 46.94,83.78 | 47.62,29.2 | 47.62,29.2 48.25,28.57 48.25,24.12 | 97.9,56.55 U$2.P$3 | C8.- 69.84,73.66 | C11.2 | 6.34,22.86 6.35,22.86 6.34,22.86
  Bottom 1.016: 55.87,83.81 58.41,83.81 | 40.63,83.81 46.94,83.81 55.87,83.81 | 22.85,83.81 26.66,83.81 | 26.66,83.81 30.47,83.81 | 30.47,83.81 40.63,83.81 | 22.85,83.81 12.69,83.81 11.42,82.55 | 11.42,82.55 SV1.2 | 22.85,83.81 SV1.10 | U$5.20 26.66,76.2 26.66,83.81 | 40.63,83.81 SV5.10 | 30.47,83.81 SV5.2 | 55.34,71.85 58.41,74.92 58.41,83.81 | 55.34,71.85 53.33,69.84 | 55.87,83.81 SV4.8 | C9.- 44.6,81.43 46.94,83.78 | C10.2 56.07,71.12 55.34,71.85 | 58.41,83.81 64.76,83.81 | 69.84,77.47 C8.- | 69.84,77.47 U$4.2 | 64.76,83.81 90.16,83.81 96.51,77.47 C1.- 99.05,67.3 99.05,57.7 97.9,56.55 | 49.52,22.86 C13.2 C18.- 55.87,24.12 v55.87,27.93 | 49.52,22.86 C12.- 49.52,16.5 44.44,16.5 43.17,17.77 R1.1 | 49.52,22.86 48.25,24.12 | 64.76,83.81 64.76,77.47 | 64.76,77.47 v64.76,76.2 | 64.76,77.47 69.84,77.47 | 69.84,73.66 73.65,69.84 QG1.7 | 6.34,17.77 C11.2 | 6.34,17.77 6.34,22.86 6.34,52.07 2.53,55.88 2.53,71.12 JP1.3 5.07,76.2 11.42,82.55 | 10.15,6.35 6.34,10.16 6.34,17.77 | 6.35,22.86 C14.-
  pour Bottom (isolate 0.813): -0.01,86.36 104.13,86.36 104.13,53.34 57.14,53.34 57.14,0 -0.01,0
GNDA
  Bottom 0.254: 68.25,27.86 U$9.18 68.18,27.84 | 68.18,27.84 68.18,27.82 66.99,27.82 66.99,31.74 U$9.12 68.25,31.74 68.26,31.75 | 68.18,27.84 68.18,27.86 70.04,27.86 | 69.84,31.75 68.26,31.75 | 68.26,31.75 68.22,31.75
  Bottom 0.406: 70.04,27.86 70.04,26.66 | U$9.1 62.39,26.03 62.41,24.56 62.42,24.01 62.46,23.97 | 62.39,21.76 R11.1 | C22.2
  Bottom 0.61: 69.84,32.58 69.84,31.75
  Bottom 0.813: 83.81,81.28 U$1.2 | IC1.3 83.81,43.18 82.54,44.45 81.27,44.45 80,43.18 80,35.55 79.41,35.55 79.37,35.59 | 86.43,31.82 C20.2 | 62.39,21.76 62.39,23.09 62.39,26.03 | C19.2 67.3,15.23 63.49,15.23
  Bottom 1.016: 93.97,35.55 90.16,35.55 | C23.2 C21.2 C22.2 70.04,26.66 70.04,23.09 62.39,23.09 | 93.97,76.2 87.62,82.55 85.08,82.55 83.81,81.28 83.81,77.47 C2.- | 90.16,35.55 C6.+ | IC4.3 72.38,40.64 C27.+ 74.92,35.55 | 90.16,35.55 80,35.55 | 79.41,35.55 74.92,35.55 | 93.97,35.55 99.97,35.55 | 93.97,12.7 93.97,15.23 | 93.97,15.23 93.97,19.05 | 93.97,19.05 93.97,31.82 | 93.97,31.82 93.97,35.55 | 93.97,12.7 U$7.P$4 U$7.P$3 | 93.97,12.7 U$7.GND | C24.2 63.49,15.23 C25.+ 62.22,11.43 62.22,8.88 | C15.2 81.27,10.16 U$7.P$3 | 93.97,19.05 C5.- | U$7.P$3 80,3.81 63.49,3.81 62.22,5.08 62.22,8.88 | 93.97,15.23 R6.1 | 93.97,31.82 86.43,31.82 | 74.92,35.55 69.84,35.55 | 69.84,35.55 69.84,32.58 | 69.84,35.55 C16.- | 62.41,24.56 C17.2 | 62.22,8.88 C28.+
  Bottom 1.27: 93.97,76.2 93.97,66.03 87.62,59.69 87.62,57.15 92.7,52.07 | 92.7,52.07 99.05,52.07 | 92.7,52.07 100.44,52.07 102.35,50.16 102.35,50.12 | 102.35,50.12 102.35,50.24 | 99.97,35.55 101,35.55 102.35,36.9 102.35,38.1 | 102.35,50.12 | 100.32,38.14 C7.+ 102.35,38.1 | 102.35,50.12 | 102.35,38.1 102.35,50.12
  pour Bottom (isolate 0.406): 59.68,0 59.68,38.1 104.13,38.1 104.13,0
N$1
  Bottom 0.813: U$4.1 67.3,81.28 68.57,82.55 74.92,82.55 76.19,81.28
  Bottom 1.27: C1.+ 86.35,67.3 83.81,67.3 76.19,74.92 76.19,81.28 | D1.C 88.89,67.3 C1.+ | U$1.1 80,80.01 78.73,78.73 78.73,74.92 83.81,69.84 C1.+
N$2  (1 unrouted)
  Bottom 0.406: 16.5,5.08 28.53,5.08 29.2,5.75 29.2,6.98 29.8,7.58 33.81,7.58 34.76,8.53 34.76,10.2 35.99,11.43 R1.2
N$3  (1 unrouted)
  Bottom 0.21: 14.28,8.88 13.21,7.81 12.02,7.81 11.9,7.93
  Bottom 0.254: 9.99,9.92 9.99,9.84 11.9,7.93
  Bottom 0.406: U$5.30 12.53,50.8 9.99,48.26 9.99,9.92
N$4
  Bottom 0.61: IC1.2 81.27,39.37 C3.+
N$5  (via drill 0.6 pad 1.68)  (2 unrouted)
  Bottom 0.61: 36.82,6.35 R1.3 | 97.78,45.72 100.32,43.18 100.32,40.64 C7.- | 97.78,45.72 IC2.5 | 97.78,45.72 v100.32,45.72
  Bottom 0.813: 36.82,6.35 v36.82,8.88
N$6  (1 unrouted)
  Bottom 0.21: 11.66,7.42 13.61,7.42
  Bottom 0.254: 9.08,9.92 9.04,9.92 9.04,9.88 11.5,7.42 11.66,7.42 | 13.61,7.42 13.77,7.58 15.75,7.58 16.98,6.35
  Bottom 0.406: U$5.29 12.85,53.34 9.04,49.53 9.04,9.92
N$7
  Bottom 0.813: U$2.P$1 92.86,56.51
  Bottom 1.27: D1.A 90.96,58.42 92.86,56.51
N$8
  Bottom 0.406: U$6.15 41.9,76.2 40.63,77.47 SV5.9
N$9
  Bottom 0.406: 35.71,72.86 38.73,69.84 40,69.84 40.63,69.21 40.63,67.94 40,67.3 38.73,67.3 38.09,66.67 38.09,62.86 38.73,62.23 40,62.23 40.63,61.59 40.63,60.32 40,59.69 38.73,59.69 38.09,59.05 38.09,57.78 39.36,56.51 U$6.30 | 35.71,72.86 | SV5.3 33.01,75.56 35.55,73.02 35.71,72.86
N$10  (1 unrouted)
  Bottom 0.406: U$5.31 12.69,48.26 11.58,47.14 11.58,27.78 12.69,26.66 15.23,26.66 15.87,26.03 15.87,19.05 17.77,17.14
N$11
  Bottom 0.406: U$6.14 45.71,69.84 45.71,72.39 48.25,74.92 SV4.1
N$12
  Bottom 0.406: U$5.12 32.14,53.34 44.44,41.03 U$8.9 | U$8.9
N$13
  Bottom 0.406: QG1.8 66.03,72.39 62.22,72.39 58.41,68.58 U$6.6
N$14
  Bottom 0.254: 46.59,36.83 45.95,37.46 45.95,41.98
  Bottom 0.305: U$8.2 52.06,36.19 51.43,36.83 46.59,36.83
  Bottom 0.406: U$6.29 39.36,48.57 45.95,41.98
N$15
  Bottom 0.406: U$8.18 35.55,34.29 27.93,34.29 27.14,35.08 27.14,39.68 25.63,41.19 25.63,54.84 26.66,55.88 U$5.13
N$16
  Bottom 0.406: U$6.12 48.25,69.84 48.25,72.39 50.79,74.92 SV4.3
N$17
  Bottom 0.406: SV4.2 46.98,80.01 46.98,74.92 44.44,72.39 U$6.13
N$18
  Bottom 0.406: U$8.25 43.97,27.93 43.17,28.73 43.17,31.11 42.46,31.82 38.89,31.82 38.17,31.11 38.17,29.6 37.78,29.2 27.46,29.2 26.11,30.55 26.11,38.97 24.12,40.95 24.12,55.88 26.66,58.42 U$5.14
N$19
  Bottom 0.61: C3.- 86.35,39.37 IC1.4
N$20
  Bottom 0.406: U$5.9 33.01,45.72 R4.2
N$21
  Bottom 0.406: U$6.11 46.98,72.39 49.52,74.92 49.52,80.01 SV4.4
N$22  (1 unrouted)
  Bottom 0.406: U$5.24 16.5,66.03 19.04,63.5 19.04,43.97 24.6,38.41 24.6,27.46 29.2,22.86 29.2,11.43 30.47,10.16
N$23
  Bottom 0.406: IC3.1 74.29,10.79 74.92,11.43 77.46,11.43 R8.1 85.08,13.96 R5.1
N$24
  Bottom 0.254: U$9.13 71.73,31.09 C22.1
N$25
  Bottom 0.406: IC3.6 71.75,22.06 72.98,23.29 78.73,23.29 | 78.73,23.29 R9.2 | 78.73,23.29 81.71,23.29 R10.1
N$26
  Bottom 0.305: U$9.17 71.07,28.49
  Bottom 0.406: 86.35,26.62 R5.2 | 71.07,28.49 84.33,28.49 86.19,26.62 86.35,26.62 | 86.35,26.62 C20.1
N$27
  Bottom 0.406: IC3.7 73.02,13.33 | R9.1 78.73,16.07 76,13.33 73.02,13.33 | R7.1 64.76,11.43 C25.- 69.84,12.7 70.48,13.33 73.02,13.33
N$28
  Bottom 0.406: IC3.3 71.75,11.62 72.3,12.18 76.27,12.18 80.6,16.5 87.62,16.5 R6.2 U$7.1
N$29
  Bottom 0.406: R7.2 72.98,6.35 | 72.98,6.35 R8.2 | IC3.2 73.02,6.38 72.98,6.35
N$30
  Bottom 0.406: U$5.15 31.74,60.96 35.55,57.15 37.42,57.15 38.09,56.47 38.09,55.2 38.73,54.57 39.92,54.57 40.59,53.89 40.59,48.57 45.91,43.25 53.25,43.25 53.93,42.58 R3.2
N$31
  Bottom 0.254: C23.1 78.73,33.02 75.76,33.02 73.18,30.44 U$9.14
  Bottom 0.406: C23.1 R10.2
N$32
  Bottom 0.254: 68.26,29.76 U$9.15 | U$9.16 68.26,29.14 | 68.26,29.76 74.21,29.76 C21.1 | 68.26,29.14 68.26,29.13 | 68.26,29.76 68.26,29.14
N$33
  Bottom 0.406: C18.+ 58.41,22.86 | 58.41,22.86 R3.1 | 58.41,22.86 R2.2
N$34
  Bottom 0.406: U$6.16 41.9,69.21 40.63,70.48 40.63,72.39 35.55,77.47 SV5.5
N$35
  Bottom 0.406: U$5.25 15.23,63.5 16.5,62.23 16.5,58.42 15.23,57.15 12.14,57.15 9,60.28 9,75.56 12.18,78.73 | 12.18,78.73 SV1.1 | 12.18,78.73
N$36
  Bottom 0.406: SV1.3 15.23,77.78 14.6,77.15 11.9,77.15 9.92,75.16 | 9.92,75.16 | 9.92,75.16 | 9.96,61.15 9.92,61.15 | 9.96,61.15 12.69,58.42 U$5.27 | 9.92,75.16 9.92,61.19 9.96,61.15
N$37
  Bottom 0.406: SV1.5 17.77,77.78 16.19,76.2 12.3,76.2 10.87,74.77 10.87,62.98 12.89,60.96 U$5.26
N$38
  Bottom 0.406: U$5.28 15.87,55.88 17.77,57.78 17.77,62.86 15.87,64.77 12.69,64.77 11.86,65.6 | SV1.9 22.85,77.78 20.31,75.24 12.77,75.24 11.86,74.33 11.86,65.6 | 11.86,65.6
N$39
  Bottom 0.406: U$6.17 34.28,76.2 34.28,79.37 33.65,80.01 32.38,80.01 31.11,78.73 SV5.1
N$40
  Bottom 0.406: U$6.9 49.52,72.39 52.06,74.92 52.06,80.01 SV4.6
N$41
  Bottom 0.254: U$9.10 56.5,32.39 56.51,32.38 54.6,32.38 52.7,34.29 52.06,34.29 | 52.06,34.29 52.06,34.3 | 46.67,34.29 52.06,34.29 | 45.48,35.48 45.48,41.23 45.12,41.59
  Bottom 0.305: 45.48,35.48 46.67,34.29
  Bottom 0.406: U$6.28 36.82,49.88 45.12,41.59 | 45.12,41.59 | 45.12,41.59
N$42
  Bottom 0.813: C26.+ IC4.2
N$43
  Bottom 0.406: U$6.7 55.87,74.92 SV4.7
N$44
  Bottom 0.406: U$6.8 50.79,69.84 50.79,72.39 53.33,74.92 SV4.5
N$45
  Bottom 0.406: C4.+ IC2.2
N$46  (via drill 0.6 pad 1.68)
  other vias: 70.48,8.17
N$47
  Bottom 0.406: IC2.4 96.51,40.64 96.51,39.37 C4.-
N$48  (via drill 0.6 pad 1.68)  (1 unrouted)
  Bottom 0.813: 76.83,49.72 76.67,49.57 75,49.57
  other vias: 76.79,49.72
N$49  (via drill 0.6 pad 1.42)
  other vias: 43.17,63.5
N$50  (via drill 0.6 pad 1.42)
  other vias: 43.17,59.69
N$52
  Bottom 0.61: IC4.4 74.92,43.18 73.65,44.45 72.38,44.45 71.11,43.18 71.11,39.37 C26.-
N$53  (1 unrouted)
  Bottom 0.406: 8.88,53.34 5.07,57.15 JP1.4
  Bottom 0.813: U$5.10 31.74,48.26
N$54  (1 unrouted)
  Bottom 0.406: 8.88,55.88 7.61,57.15 JP1.2
  Bottom 0.813: U$5.11 31.74,50.8
N$55  (via drill 0.6 pad 1.42)
  other vias: 8.88,55.88
N$56  (via drill 0.6 pad 1.42)
  other vias: 8.88,53.34
N$58  (via drill 0.6 pad 1.68)
  other vias: 31.74,50.8
N$59  (via drill 0.6 pad 1.68)
  other vias: 31.74,48.26
N$60
  Bottom 0.61: 91.43,44.45 93.97,44.45 95.24,43.18 IC2.3 | IC1.5 86.35,50.8 87.62,52.07 90.16,52.07 91.43,50.8 91.43,44.45 | 91.43,44.45 89.65,44.45 88.26,43.06 88.26,38.77 87.58,38.1 C6.-
N$64
  Bottom 0.406: IC3.5 70.48,15.27 | 70.44,15.2 70.44,15.27 IC3.5 | IC3.5 70.48,16.5 | 70.48,16.5 70.48,19.05 | 70.48,19.05 70.48,20.95 R11.2 | 70.48,19.05 R2.1 | 70.48,16.5 C24.1

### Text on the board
Bottom: 2006 | eOscope | Ver1.2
